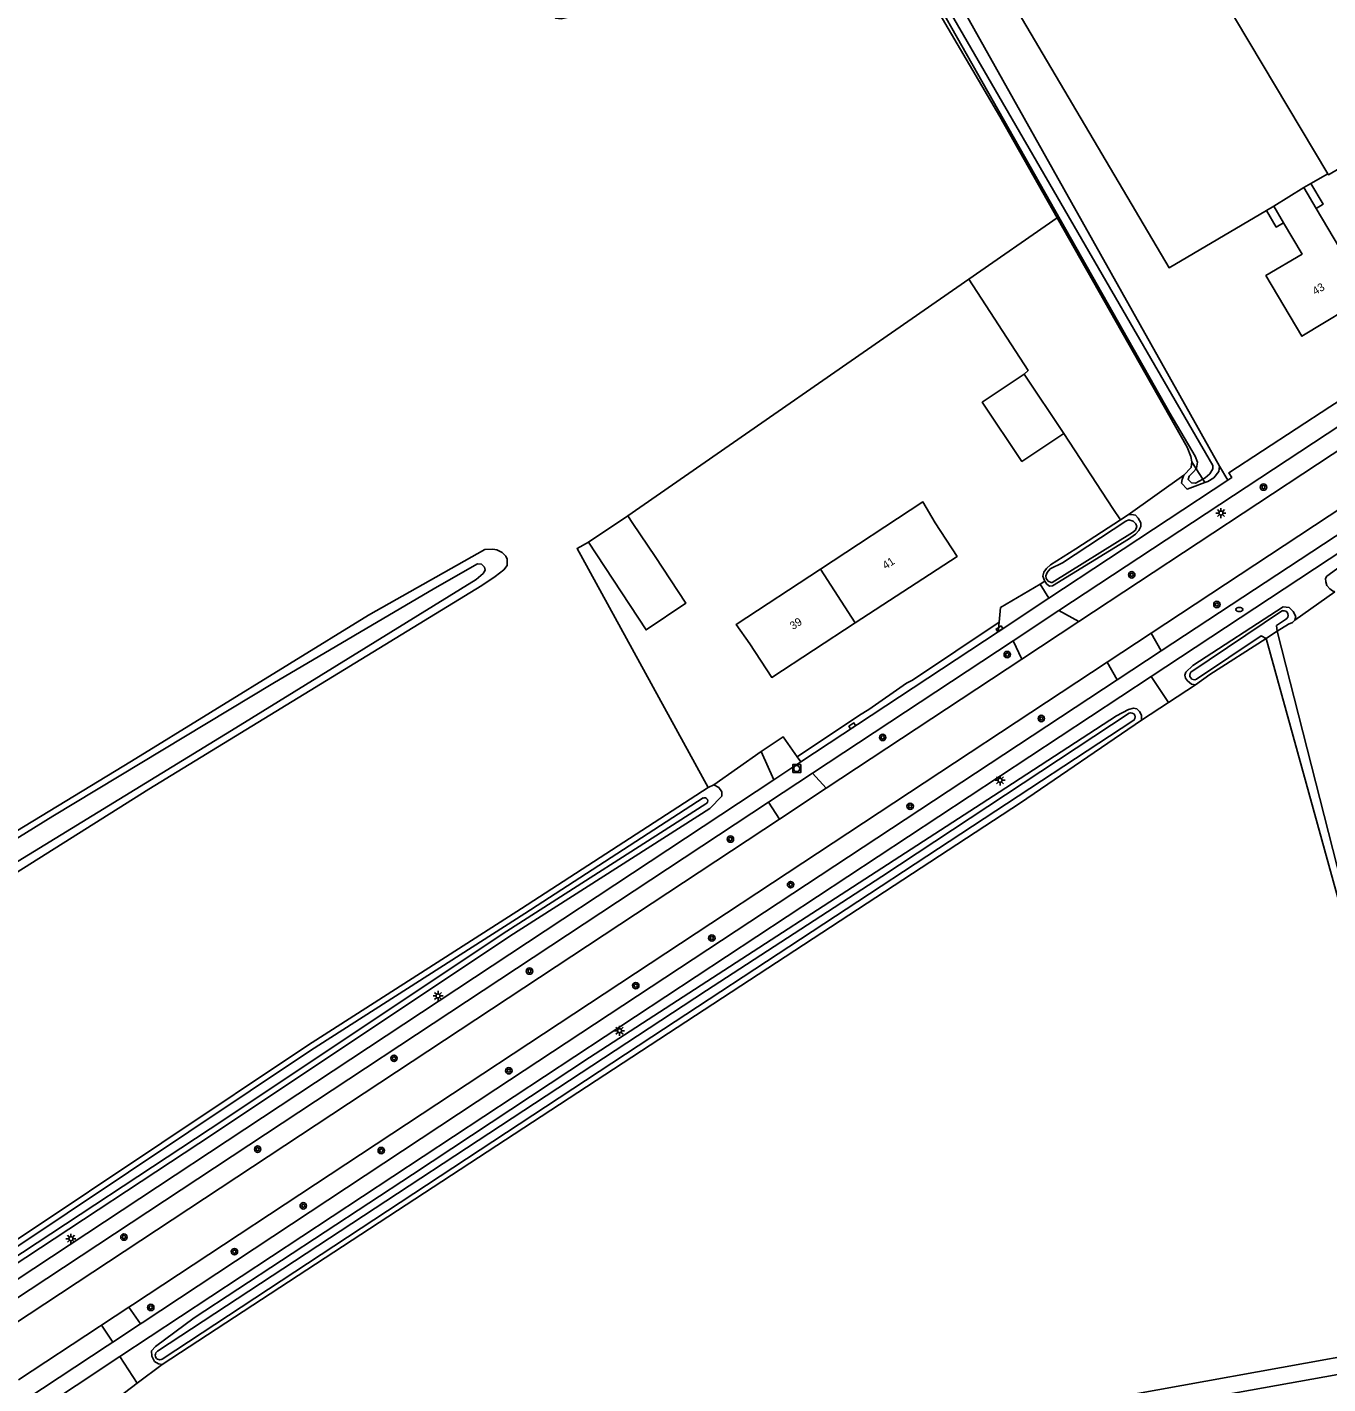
# Model space of a CAD drawing. Extents: x 140000 to 143000, y 403500 to 406000.
# Drawn here: x 140683.1 to 140845.6, y 404635.1 to 404804.7 of the extents above; entities that cross this region are included whole.
import ezdxf

# ---------------------------------------------------------------- set-up
doc = ezdxf.new("R2010")
doc.units = 0
for name, color, linetype in [('gg-afsc-erfafscheiding', 7, 'Continuous'), ('gg-afsc-hekwerk', 7, 'Continuous'), ('gg-anno-huisnummerreeks BGT', 7, 'Continuous'), ('gg-bbg-bijgebouw', 7, 'Continuous'), ('gg-bbg-gedigitaliseerde bijgebouw', 7, 'Continuous'), ('gg-bbg-hoofdgebouw', 7, 'Continuous'), ('gg-bbg-luifel en loopbrug', 7, 'Continuous'), ('gg-bbg-tussenscheiding', 7, 'Continuous'), ('gg-knt-bronhoudergrens', 7, 'Continuous'), ('gg-knt-verharding', 7, 'Continuous'), ('gg-knt-verharding nz', 7, 'Continuous'), ('gg-kntw-bovenkant insteek waterloop', 7, 'Continuous'), ('gg-kntw-waterlijn', 7, 'Continuous'), ('gt-grn-groengrens', 7, 'Continuous'), ('gt-grn-vlakafsluiter', 7, 'Continuous'), ('gt-grn-weggrens', 7, 'Continuous'), ('gt-symb-boom', 7, 'Continuous'), ('gt-symb-brandkraan', 7, 'Continuous'), ('gt-symb-kolk', 7, 'Continuous'), ('gt-symb-lichtmast', 7, 'Continuous'), ('gt-symb-rioolschacht', 7, 'Continuous')]:
    doc.layers.add(name, color=color, linetype=linetype)

# ---------------------------------------------------------------- blocks, each defined once
blk = doc.blocks.new('gt0-BOOM')
at = {"layer": 'gt-symb-boom'}
for radius in [0.4, 0.2]:
    blk.add_circle((0, 0), radius, dxfattribs=at)
blk = doc.blocks.new('gt0-BR')
at = {"layer": 'gt-symb-brandkraan'}
for centre, radius, start, end in [((-0.24, 0), 0.206, 107.5669, 252.4331), ((0.6, -2.66), 3, 106.892, 107.5669), ((0, -0.69), 0.938, 73.108, 106.892), ((-0.6, -2.66), 3, 72.4331, 73.108), ((0.24, 0), 0.206, 287.567, 72.4331), ((0.6, 2.66), 3, 252.4331, 253.108), ((0, 0.69), 0.938, 253.108, 286.8921), ((-0.6, 2.66), 3, 286.8921, 287.567)]:
    blk.add_arc(centre, radius, start, end, dxfattribs=at)
blk = doc.blocks.new('gt0-LMAST')
at = {"layer": 'gt-symb-lichtmast'}
for p, q in [((-0.18, 0.17), (-0.45, 0.44)), ((-0.01, 0.25), (-0.01, 0.62)), ((0.17, 0.17), (0.44, 0.44)), ((-0.26, 0), (-0.63, 0)), ((-0.18, -0.18), (-0.45, -0.45)), ((-0.01, -0.25), (-0.01, -0.63)), ((0.44, -0.45), (0.17, -0.18)), ((0.24, 0), (0.62, 0))]:
    blk.add_line(p, q, dxfattribs=at)
blk.add_circle((-0.01, 0), 0.25, dxfattribs=at)
blk = doc.blocks.new('gt0-KOLK')
at = {"layer": 'gt-symb-kolk'}
blk.add_lwpolyline([(0, 0), (0.38, 0), (0.38, 0.4), (-0.37, 0.4), (-0.37, 0), (0, 0)], dxfattribs=at)
blk = doc.blocks.new('gt0-RS')
at = {"layer": 'gt-symb-rioolschacht'}
blk.add_lwpolyline([(-0.5, -0.5), (0.5, -0.5), (0.5, 0.5), (-0.5, 0.5)], close=True, dxfattribs=at)
blk.add_circle((0, 0), 0.375, dxfattribs=at)

msp = doc.modelspace()

# ---------------------------------------------------------------- linework, layer by layer
at = {"layer": 'gg-afsc-erfafscheiding'}
for p, q in [((140833.11, 404748.07), (140832.08, 404749.79)), ((140810.24, 404735.45), (140809.67, 404735.08)), ((140841.52, 404730.56), (140846.51, 404734.12)), ((140768.91, 404709.97), (140774.83, 404714.14))]:
    msp.add_line(p, q, dxfattribs=at)
for points in [[(140800.78, 404773.19), (140808.17, 404761.74), (140807.69, 404761.31)], [(140779.33, 404713.48), (140787.09, 404718.69), (140788.26, 404719.38), (140792.98, 404722.67), (140793.74, 404723.05), (140804.54, 404730.3)]]:
    msp.add_lwpolyline(points, dxfattribs=at)
at = {"layer": 'gg-afsc-hekwerk'}
msp.add_line((140768.2, 404709.66), (140751.81, 404739.53), dxfattribs=at)
at = {"layer": 'gg-bbg-bijgebouw'}
for p, q in [((140842.63, 404784.61), (140843.5, 404785.11)), ((140845.62, 404786.34), (140843.5, 404785.11)), ((140838.88, 404782.29), (140837.96, 404781.75)), ((140812.64, 404753.9), (140807.69, 404761.31))]:
    msp.add_line(p, q, dxfattribs=at)
for points in [[(140820.35, 404828.94), (140808.81, 404848.56), (140789, 404836.9), (140825.78, 404774.61), (140837.96, 404781.75)], [(140812.64, 404753.9), (140807.39, 404750.39), (140802.44, 404757.8), (140807.69, 404761.31)]]:
    msp.add_lwpolyline(points, dxfattribs=at)
at = {"layer": 'gg-bbg-gedigitaliseerde bijgebouw'}
for p, q in [((140753.25, 404740.32), (140758.15, 404743.61)), ((140758.15, 404743.61), (140758.79, 404742.66))]:
    msp.add_line(p, q, dxfattribs=at)
msp.add_lwpolyline([(140758.79, 404742.66), (140761.58, 404738.51), (140765.39, 404732.67), (140760.43, 404729.34), (140753.25, 404740.32)], dxfattribs=at)
at = {"layer": 'gg-bbg-hoofdgebouw'}
for p, q in [((140842.63, 404784.61), (140844.17, 404782.02)), ((140838.88, 404782.29), (140840.1, 404780.23))]:
    msp.add_line(p, q, dxfattribs=at)
for points in [[(140831.15, 404810.59), (140848.53, 404820.83), (140862.94, 404796.45), (140845.69, 404786.22), (140845.62, 404786.34)], [(140840.1, 404780.23), (140842.41, 404776.31), (140837.89, 404773.62), (140842.39, 404766.05), (140850.68, 404771.06), (140844.17, 404782.02)], [(140786.57, 404730.22), (140799.3, 404738.52), (140796.56, 404742.71), (140795.03, 404745.33), (140782.24, 404736.95)], [(140786.57, 404730.22), (140776.13, 404723.4), (140773.4, 404727.59), (140771.67, 404730.02), (140782.24, 404736.95)]]:
    msp.add_lwpolyline(points, dxfattribs=at)
at = {"layer": 'gg-bbg-luifel en loopbrug'}
for points in [[(140844.17, 404782.02), (140845.03, 404782.53), (140843.5, 404785.11)], [(140840.1, 404780.23), (140839.19, 404779.69), (140837.96, 404781.75)]]:
    msp.add_lwpolyline(points, dxfattribs=at)
at = {"layer": 'gg-bbg-tussenscheiding'}
for p, q in [((140831.15, 404810.59), (140845.62, 404786.34)), ((140842.63, 404784.61), (140838.88, 404782.29)), ((140786.57, 404730.22), (140782.24, 404736.95))]:
    msp.add_line(p, q, dxfattribs=at)
at = {"layer": 'gg-knt-bronhoudergrens'}
for p, q in [((140800.78, 404773.19), (140811.8, 404780.83)), ((140758.15, 404743.61), (140800.78, 404773.19))]:
    msp.add_line(p, q, dxfattribs=at)
at = {"layer": 'gg-knt-verharding'}
for p, q in [((140833.11, 404748.07), (140810.78, 404733.33)), ((140823.53, 404728.93), (140852.74, 404748.19)), ((140824.81, 404726.72), (140854.63, 404746.37)), ((140823.56, 404723.54), (140856.67, 404745.36)), ((140810.78, 404733.33), (140809.67, 404735.08)), ((140810.78, 404733.33), (140804.41, 404729.12)), ((140806.3, 404727.98), (140812.02, 404731.75)), ((140812.02, 404731.75), (140814.52, 404730.38)), ((140804.41, 404729.12), (140779.77, 404712.86)), ((140804.41, 404729.12), (140804.54, 404730.3)), ((140781.21, 404711.44), (140806.3, 404727.98)), ((140806.3, 404727.98), (140807.38, 404725.67)), ((140824.81, 404726.72), (140823.53, 404728.93)), ((140824.81, 404726.72), (140819.31, 404723.1)), ((140807.38, 404725.67), (140782.94, 404709.55)), ((140818.03, 404725.3), (140819.31, 404723.1)), ((140694.66, 404638.53), (140823.56, 404723.54)), ((140776.39, 404710.62), (140774.83, 404714.14)), ((140779.77, 404712.86), (140776.39, 404710.62)), ((140779.77, 404712.86), (140779.33, 404713.48)), ((140775.72, 404707.82), (140781.21, 404711.44)), ((140781.21, 404711.44), (140782.94, 404709.55)), ((140676.97, 404642.65), (140775.72, 404707.82)), ((140775.72, 404707.82), (140777.1, 404705.7)), ((140678.98, 404641), (140777.1, 404705.7)), ((140692.39, 404642.47), (140695.8, 404644.72)), ((140697.23, 404642.62), (140693.78, 404640.34)), ((140602.96, 404578.05), (140694.66, 404638.53))]:
    msp.add_line(p, q, dxfattribs=at)
for points in [[(140883.47, 404780.75), (140863.16, 404768.28), (140845.88, 404757.2), (140833.25, 404748.96), (140833.61, 404748.4), (140833.11, 404748.07)], [(140812.02, 404731.75), (140850.54, 404757.15), (140858.07, 404761.99), (140859.79, 404763.1), (140861.74, 404764.31), (140863.16, 404765.2)], [(140814.52, 404730.38), (140851.8, 404754.96), (140859.43, 404759.87)], [(140819.7, 404743.09), (140818.76, 404744.5), (140812.64, 404753.9)], [(140753.25, 404740.32), (140751.81, 404739.53), (140768.2, 404709.66)], [(140804.54, 404730.3), (140804.73, 404732.14), (140809.67, 404735.08)], [(140818.03, 404725.3), (140696.23, 404645), (140695.8, 404644.72)], [(140819.31, 404723.1), (140741.66, 404671.94), (140697.44, 404642.76), (140697.23, 404642.62)], [(140774.83, 404714.14), (140777.55, 404715.99), (140779.33, 404713.48)], [(140776.39, 404710.62), (140679.46, 404646.64), (140675.89, 404644.29)], [(140682, 404635.62), (140692.11, 404642.29), (140692.39, 404642.47)], [(140683.05, 404633.26), (140693.09, 404639.89), (140693.78, 404640.34)]]:
    msp.add_lwpolyline(points, dxfattribs=at)
at = {"layer": 'gg-knt-verharding nz'}
for p, q in [((140814.52, 404730.38), (140807.38, 404725.67)), ((140823.53, 404728.93), (140818.03, 404725.3)), ((140777.1, 404705.7), (140782.94, 404709.55))]:
    msp.add_line(p, q, dxfattribs=at)
at = {"layer": 'gg-kntw-bovenkant insteek waterloop'}
for p, q in [((140819.7, 404743.09), (140820.66, 404743.72)), ((140839.29, 404729.17), (140850.29, 404685.98)), ((140768.2, 404709.66), (140768.91, 404709.97))]:
    msp.add_line(p, q, dxfattribs=at)
for points in [[(140811.8, 404780.83), (140804.63, 404793.48), (140792.15, 404814.81), (140791.74, 404814.93), (140790.6, 404815.01), (140749.81, 404805.72), (140749.11, 404805.78), (140748.38, 404806.5), (140747.55, 404807.55), (140725.66, 404845.32), (140706.91, 404876.58)], [(140711.41, 404875.05), (140711.98, 404873.45), (140713.28, 404871.32), (140714.8, 404868.72), (140733.42, 404838.9), (140750.44, 404810), (140751.17, 404809.74), (140752.92, 404810.1), (140792.31, 404818.86), (140793.25, 404818.45), (140794.13, 404817.46), (140832.08, 404749.79)], [(140811.8, 404780.83), (140828.03, 404752.17), (140828.51, 404751), (140828.63, 404750.36)], [(140828.63, 404750.36), (140828.54, 404749.63), (140827.61, 404748.69)], [(140832.08, 404749.79), (140832, 404749.12), (140831.36, 404748.35), (140830.63, 404747.91), (140830.25, 404747.77)], [(140830.25, 404747.77), (140828.73, 404747.17), (140828.03, 404746.93), (140827.32, 404747.69), (140827.41, 404748.13), (140827.61, 404748.69)], [(140810.24, 404735.45), (140810.2, 404735.5), (140809.99, 404736.05), (140810.14, 404736.54), (140810.45, 404737.01), (140810.96, 404737.48), (140814.15, 404739.49), (140819.7, 404743.09)], [(140810.24, 404735.45), (140810.52, 404735.07), (140810.84, 404734.79), (140811.2, 404734.85), (140820.73, 404740.69), (140821.57, 404741.31), (140822, 404741.75), (140822.24, 404742.26), (140822.26, 404742.73), (140821.94, 404743.31), (140821.58, 404743.67), (140821.11, 404743.76), (140820.66, 404743.72)], [(140846.51, 404734.12), (140846.19, 404734.21), (140845.89, 404734.47), (140845.49, 404734.91), (140845.37, 404735.36), (140845.33, 404735.77), (140845.5, 404736.05), (140851.76, 404740.6), (140854.95, 404742.95), (140855.8, 404743.23), (140856.72, 404743.22), (140857.21, 404743.03), (140857.68, 404742.56), (140857.95, 404742.15), (140857.92, 404741.81)], [(140668.86, 404690.92), (140698.27, 404709.44), (140739.89, 404734.88), (140741.57, 404736.02), (140742.65, 404736.85), (140743.05, 404737.41), (140743.08, 404738.17), (140742.91, 404738.58), (140742.45, 404739.01), (140741.77, 404739.34), (140741.26, 404739.44), (140740.27, 404739.38), (140725.73, 404731.17), (140696.12, 404712.93), (140666.22, 404694.8)], [(140841.52, 404730.56), (140841.61, 404731.03), (140841.31, 404731.63), (140840.78, 404732.15), (140840.06, 404732.23), (140828.77, 404724.91), (140827.87, 404724.08), (140827.76, 404723.7), (140827.82, 404723.31), (140828.1, 404722.99), (140828.57, 404722.56), (140829.08, 404722.47)], [(140839.29, 404729.17), (140840.69, 404730.06), (140841.22, 404730.26), (140841.52, 404730.56)], [(140837.9, 404728.28), (140830.88, 404723.79), (140829.08, 404722.47)], [(140837.9, 404728.28), (140848.23, 404690.91), (140849.57, 404683.94)], [(140822.36, 404718.07), (140822.32, 404718.69), (140822.1, 404719.13), (140821.77, 404719.47), (140821.34, 404719.58), (140820.72, 404719.4), (140819.2, 404718.59), (140804.57, 404709.05), (140753.37, 404675.91), (140731.24, 404661.29), (140703.96, 404643.39), (140699.13, 404639.79), (140698.64, 404639.26), (140698.68, 404638.57), (140699.01, 404637.93), (140699.49, 404637.65), (140699.97, 404637.56)], [(140822.36, 404718.07), (140807.23, 404707.73), (140699.97, 404637.56)], [(140768.91, 404709.97), (140769.53, 404709.64), (140769.9, 404709.11), (140769.88, 404708.57), (140768.38, 404707.02), (140743.42, 404691.07), (140706.36, 404666.36), (140681.08, 404649.73), (140680.24, 404649.1), (140679.49, 404648.82), (140678.51, 404648.75), (140677.99, 404648.86), (140676.95, 404649.46), (140676.55, 404649.84)], [(140681.71, 404653.1), (140718.1, 404677.43), (140744.86, 404694.52), (140768.19, 404709.65), (140768.2, 404709.66)], [(140852.27, 404639.42), (140802.45, 404630.41), (140706.44, 404612.8)], [(140706.96, 404610.44), (140759.3, 404620.58), (140852.93, 404637.38)]]:
    msp.add_lwpolyline(points, dxfattribs=at)
at = {"layer": 'gg-kntw-waterlijn'}
msp.add_line((140839.97, 404731.75), (140828.52, 404724.06), dxfattribs=at)
for points in [[(140707.98, 404879.18), (140708.68, 404878.03), (140729.03, 404843.97), (140749.53, 404809.03), (140750.38, 404808.71), (140751.7, 404808.8), (140790.76, 404817.41), (140791.64, 404817.36), (140792.11, 404816.95), (140792.79, 404816.28), (140831.26, 404749.91), (140831.26, 404749.49), (140830.86, 404748.85), (140830.3, 404748.35), (140829.99, 404748.18)], [(140829.17, 404749.49), (140829.21, 404749.54), (140829.33, 404750.31), (140829.03, 404751.07), (140825.9, 404756.44), (140792.77, 404814.96), (140791.86, 404815.58), (140790.86, 404815.57), (140789.31, 404815.42), (140749.81, 404806.83), (140749.16, 404807.01), (140748.37, 404807.79), (140706.37, 404878.21)], [(140829.17, 404749.49), (140828.84, 404749.1), (140828.31, 404748.57), (140828.17, 404748.13), (140828.58, 404747.73), (140829.08, 404747.7), (140829.99, 404748.18)], [(140810.57, 404736.51), (140810.4, 404736.12), (140810.41, 404735.78), (140810.67, 404735.44), (140811.05, 404735.25), (140811.18, 404735.27), (140821.22, 404741.51), (140821.59, 404741.81), (140821.74, 404742.26), (140821.64, 404742.58), (140821.3, 404742.92), (140820.76, 404743.12), (140820.4, 404742.95), (140812.47, 404737.74), (140810.93, 404736.98), (140810.57, 404736.51)], [(140666.49, 404693.82), (140686.3, 404706.09), (140713.78, 404722.64), (140734.01, 404734.58), (140739.35, 404737.6), (140739.86, 404737.55), (140740.25, 404737.18), (140740.3, 404736.83), (140740.06, 404736.38), (140739.19, 404735.65), (140709.17, 404717.11), (140677.28, 404697.6), (140668.01, 404691.67)], [(140840.34, 404730.64), (140839.2, 404729.88), (140839.29, 404729.17)], [(140829.2, 404723.17), (140837.29, 404728.6), (140837.9, 404728.28)], [(140820.78, 404718.95), (140789.9, 404698.53), (140767.99, 404684.27), (140699.37, 404639.2)], [(140699.95, 404638.22), (140761.16, 404678.5), (140821.27, 404717.97)], [(140677.79, 404650.79), (140678.52, 404649.73), (140678.94, 404649.53), (140679.33, 404649.56), (140679.88, 404649.76), (140680.65, 404650.34), (140705.95, 404666.99), (140743.01, 404691.7), (140767.9, 404707.6)], [(140679.65, 404652.22), (140680.54, 404651.43), (140718.51, 404676.8), (140745.27, 404693.89), (140767.55, 404708.34)]]:
    msp.add_lwpolyline(points, dxfattribs=at)
for centre, radius, start, end in [((140840.08, 404731.17), 0.586, 296.1337, 100.705), ((140828.94, 404723.68), 0.567, 137.5755, 296.8222), ((140821, 404718.44), 0.549, 299.6873, 113.4428), ((140767.72, 404707.97), 0.409, 295.9673, 115.4713), ((140699.66, 404638.71), 0.569, 120.018, 301.3571)]:
    msp.add_arc(centre, radius, start, end, dxfattribs=at)
at = {"layer": 'gt-grn-groengrens'}
for p, q in [((140820.66, 404743.72), (140827.61, 404748.69)), ((140829.08, 404722.47), (140825.72, 404720.27)), ((140825.72, 404720.27), (140822.36, 404718.07)), ((140696.84, 404635.22), (140699.97, 404637.56)), ((140693.65, 404632.82), (140696.84, 404635.22))]:
    msp.add_line(p, q, dxfattribs=at)
at = {"layer": 'gt-grn-vlakafsluiter'}
for p, q in [((140828.63, 404750.36), (140829.17, 404749.49)), ((140829.17, 404749.49), (140829.99, 404748.18)), ((140830.25, 404747.77), (140829.99, 404748.18))]:
    msp.add_line(p, q, dxfattribs=at)
msp.add_lwpolyline([(140837.9, 404728.28), (140838.45, 404728.63), (140839.29, 404729.17)], dxfattribs=at)
at = {"layer": 'gt-grn-weggrens'}
for p, q in [((140823.56, 404723.54), (140825.72, 404720.27)), ((140697.23, 404642.62), (140695.8, 404644.72)), ((140693.78, 404640.34), (140692.39, 404642.47)), ((140694.66, 404638.53), (140696.84, 404635.22))]:
    msp.add_line(p, q, dxfattribs=at)

# ---------------------------------------------------------------- block references
at = {"layer": 'gt-symb-boom'}
for p in [(140837.59, 404747.19), (140821.12, 404736.23), (140831.76, 404732.52), (140805.56, 404726.26), (140809.82, 404718.27), (140790, 404715.91), (140793.43, 404707.3), (140770.97, 404703.2), (140778.49, 404697.51), (140768.65, 404690.84), (140745.86, 404686.71), (140759.14, 404684.89), (140728.93, 404675.81), (140743.28, 404674.26), (140711.89, 404664.46), (140727.33, 404664.28), (140717.59, 404657.38), (140695.18, 404653.47), (140708.99, 404651.65), (140698.53, 404644.68)]:
    msp.add_blockref('gt0-BOOM', p, dxfattribs=at)
at = {"layer": 'gt-symb-brandkraan'}
msp.add_blockref('gt0-BR', (140834.56, 404731.9), dxfattribs=at)
at = {"layer": 'gt-symb-kolk'}
for p, rotation in [((140804.7, 404729.31), 33.43491397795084), ((140786.3, 404717.17), 33.434913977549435)]:
    msp.add_blockref('gt0-KOLK', p, dxfattribs=dict(at, rotation=rotation))
at = {"layer": 'gt-symb-lichtmast'}
for p in [(140832.28, 404743.95), (140804.67, 404710.55), (140734.44, 404683.61), (140757.12, 404679.26), (140688.56, 404653.27)]:
    msp.add_blockref('gt0-LMAST', p, dxfattribs=at)
at = {"layer": 'gt-symb-rioolschacht'}
msp.add_blockref('gt0-RS', (140779.25, 404712.01), dxfattribs=at)

# ---------------------------------------------------------------- texts
at = {"layer": 'gg-anno-huisnummerreeks BGT'}
for s, rotation, p in [('43', 31.1, (140844.06, 404771.15)), ('41', 33.1, (140790.37, 404736.87)), ('39', 33.1, (140778.79, 404729.31))]:
    msp.add_text(s, height=1, rotation=rotation, dxfattribs=at).set_placement(p)

doc.saveas('drawing.dxf')
